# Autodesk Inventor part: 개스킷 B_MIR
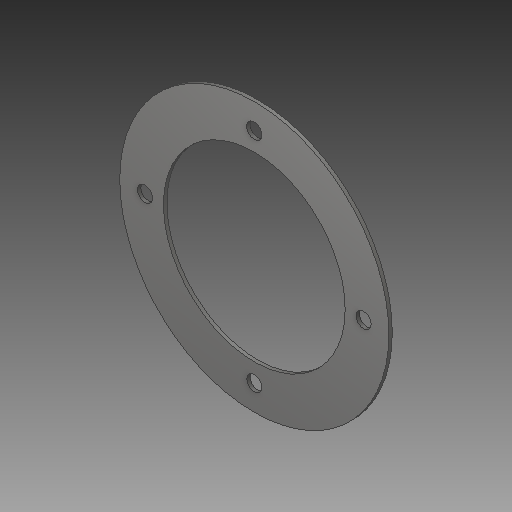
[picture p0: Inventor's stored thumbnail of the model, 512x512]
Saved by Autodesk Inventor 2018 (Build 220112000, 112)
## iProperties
Created: 2019-10
Part Number: 개스킷 B_MIR
Material: 고무
Document SubType Name: Modeling
Designer: expoc
Density: 0.93 g/cm^3
Appearance: 고무 - 검은색 - 버전 1.1
Author: mduedu
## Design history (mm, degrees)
derived "개스킷 B.ipt"
  sketch "스케치1"
    geometry: C1 r 40 at (0, 0) reference; C2 r 27 at (0, 0) reference; 1 further point
    dimensions: "d0" = 10 dimension on point (0, 0) C1.centre C1 C2.centre C2
  sketch "스케치2"
    geometry: C1 r 2.25 at (0, 32.5) reference; 2 further points
    constraints: 1 vertical alignment
    dimensions: "d0" = 10 dimension on point (0, 0) point (0, 0) C1.centre C1
feature "솔리드1::개스킷 B.ipt" dims "d0" = 10
tag "피쳐 태그1"
node "솔리드1"
